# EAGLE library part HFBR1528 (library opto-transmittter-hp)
OPTO TRANSMITTER
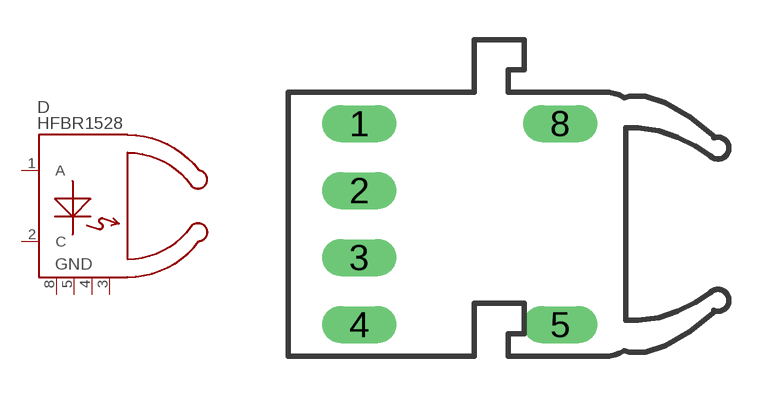
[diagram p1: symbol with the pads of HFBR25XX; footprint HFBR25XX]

Designator prefix D

## HFBR1528  [HFBR25XX]
1  A  pas
2  C  pas
3  1  pas
4  4  pas
5  GND  pas
8  GND  pas

## Footprint HFBR25XX (pad centres in mm)
OPTO RECEIVER
drill 0.9 long: 1 0,3.81; 2 0,1.27; 3 0,-1.27; 4 0,-3.81; 5 7.62,-3.81; 8 7.62,3.81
